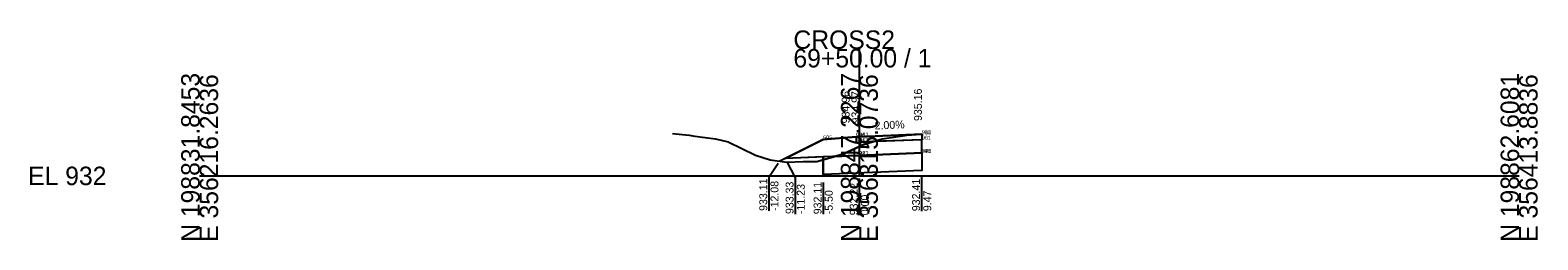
# Model space of a CAD drawing. Extents: x -26 to 203, y -10 to 14021.
# Drawn here: x -25.7 to 202.8, y 10490.3 to 10522.1 of the extents above; entities that cross this region are included whole.
import ezdxf

# ---------------------------------------------------------------- set-up
doc = ezdxf.new("R2010")
doc.units = 0
for name, color, linetype in [('Default', 7, 'Continuous'), ('P_E_XS_Ground', 7, 'Continuous'), ('P_XS', 7, 'Continuous'), ('P_XS_Bold', 7, 'Continuous'), ('P_XS_EAR_CommonGrnd', 7, 'Continuous'), ('P_XS_Lane', 7, 'Continuous'), ('P_XS_Rock', 7, 'Continuous')]:
    doc.layers.add(name, color=color, linetype=linetype)

msp = doc.modelspace()

# ---------------------------------------------------------------- linework, layer by layer
at = {"layer": 'Default'}
for p, q in [((100, 10500), (100, 10519.24)), ((0, 10500), (100, 10500)), ((100, 10500), (200, 10500))]:
    msp.add_line(p, q, dxfattribs=at)
at = {"layer": 'P_E_XS_Ground'}
for p, q in [((71.66, 10506.41), (74.2, 10506.18)), ((74.2, 10506.18), (75.08, 10506)), ((75.08, 10506), (78.17, 10505.61)), ((103.45, 10505.6), (106.59, 10506.07)), ((106.59, 10506.07), (107.21, 10506.19)), ((107.21, 10506.19), (109.29, 10506.31)), ((109.29, 10506.31), (109.49, 10506.32)), ((78.17, 10505.61), (80.11, 10505.17)), ((80.11, 10505.17), (84.27, 10503.12)), ((97.48, 10503.3), (100, 10504.46)), ((100, 10504.46), (100.69, 10504.78)), ((100.69, 10504.78), (103.45, 10505.6)), ((84.27, 10503.12), (86.48, 10502.43)), ((86.48, 10502.43), (89.02, 10502.07)), ((89.02, 10502.07), (91.5, 10502.2)), ((91.5, 10502.2), (93.55, 10502.19)), ((93.55, 10502.19), (97.48, 10503.3))]:
    msp.add_line(p, q, dxfattribs=at)
at = {"layer": 'P_XS'}
for p, q in [((99.5, 10505.92), (99.5, 10505.08)), ((109.47, 10506.32), (109.47, 10505.48)), ((99.5, 10505.08), (100, 10505.1)), ((109.47, 10505.48), (99.99, 10505.1)), ((109.47, 10503.48), (99.99, 10503.1)), ((109.47, 10503.48), (109.47, 10505.48)), ((109.47, 10503.48), (109.47, 10500.81)), ((99.5, 10503.08), (88.77, 10502.65)), ((94.5, 10502.88), (94.5, 10500.21)), ((99.5, 10503.08), (100, 10503.1)), ((109.47, 10500.81), (94.5, 10500.21))]:
    msp.add_line(p, q, dxfattribs=at)
at = {"layer": 'P_XS_EAR_CommonGrnd'}
for points in [[(99.5, 10505.92), (99.5, 10505.08), (99.99, 10505.1), (100, 10505.1), (102.07, 10505.19), (100.69, 10504.78), (100, 10504.46), (97.48, 10503.3), (96.26, 10502.95), (94.5, 10502.88), (88.77, 10502.65), (94.5, 10505.52)], [(99.5, 10505.92), (99.5, 10505.08), (99.99, 10505.1), (100, 10505.1), (102.07, 10505.19), (103.45, 10505.6), (106.59, 10506.07), (107.21, 10506.19), (109.29, 10506.31), (109.47, 10506.32), (100, 10505.94)], [(109.47, 10506.32), (109.47, 10505.48), (102.07, 10505.19), (103.45, 10505.6), (106.59, 10506.07), (107.21, 10506.19), (109.29, 10506.31)], [(99.99, 10503.1), (100, 10503.1), (109.47, 10503.48), (109.47, 10500.81), (94.5, 10500.21), (94.5, 10502.46), (96.26, 10502.95), (99.5, 10503.08)], [(99.99, 10503.1), (100, 10503.1), (109.47, 10503.48), (109.47, 10505.48), (102.07, 10505.19), (100.69, 10504.78), (100, 10504.46), (97.48, 10503.3), (96.26, 10502.95), (99.5, 10503.08)], [(89.02, 10502.07), (91.5, 10502.2), (93.55, 10502.19), (94.5, 10502.46), (94.5, 10502.88), (88.77, 10502.65), (87.92, 10502.23)], [(94.5, 10502.46), (96.26, 10502.95), (94.5, 10502.88)]]:
    msp.add_lwpolyline(points, close=True, dxfattribs=at)
at = {"layer": 'P_XS_Lane'}
for p, q in [((99.5, 10505.92), (94.5, 10505.52)), ((99.5, 10505.92), (100, 10505.94)), ((100, 10505.94), (109.47, 10506.32)), ((94.5, 10505.52), (87.92, 10502.23))]:
    msp.add_line(p, q, dxfattribs=at)
at = {"layer": 'P_XS_Rock'}
for p, q in [((87.68, 10501.86), (86.28, 10499.78)), ((90.27, 10499.81), (89.06, 10502.12)), ((86.28, 10499.78), (86.28, 10494.69)), ((90.27, 10499.81), (90.27, 10494.22)), ((94.51, 10498.98), (94.51, 10494.18)), ((99.99, 10499.62), (99.99, 10494.03)), ((109.44, 10499.94), (109.44, 10494.65))]:
    msp.add_line(p, q, dxfattribs=at)

# ---------------------------------------------------------------- texts
at = {"layer": 'Default'}
for s, p in [('CROSS2', (90, 10519.24)), ('69+50.00 / 1', (90, 10516.44)), ('EL 932', (-26, 10498.6))]:
    msp.add_text(s, height=2.8, dxfattribs=at).set_placement(p)
for s, p in [('N 198831.8453', (0, 10490)), ('E 356216.2636', (2.8, 10490)), ('N 198847.2267', (100, 10490)), ('E 356315.0736', (102.8, 10490)), ('N 198862.6081', (200, 10490)), ('E 356413.8836', (202.8, 10490))]:
    msp.add_text(s, height=2.8, rotation=90, dxfattribs=at).set_placement(p)
at = {"layer": 'P_XS_Bold'}
for s, p in [('505', (94.5, 10505.52)), ('951', (99.5, 10505.92)), ('9', (99.5, 10505.92)), ('900', (99.5, 10505.92)), ('961', (99.5, 10505.08)), ('962', (99.99, 10505.1)), ('952', (100, 10505.94)), ('952', (100, 10505.94)), ('962', (100, 10505.1)), ('951', (109.47, 10506.32)), ('9', (109.47, 10506.32)), ('900', (109.47, 10506.32)), ('910', (109.47, 10506.32)), ('961', (109.47, 10505.48)), ('971', (99.5, 10503.08)), ('998', (99.5, 10503.08)), ('972', (99.99, 10503.1)), ('972', (100, 10503.1)), ('540', (109.47, 10503.48)), ('971', (109.47, 10503.48)), ('998', (109.47, 10503.48))]:
    msp.add_text(s, height=0.6, dxfattribs=at).set_placement(p)
at = {"layer": 'P_XS_Rock'}
for s, rotation, p in [('934.96', 90, (98.52, 10507.96)), ('934.97', 90, (100, 10507.94)), ('934.97', 90, (100, 10507.94)), ('934.97', 90, (100, 10507.94)), ('934.97', 90, (100, 10507.94)), ('935.16', 90, (109.47, 10508.32)), ('2.00%', 2.2906, (102.33, 10507.03)), ('933.11', 90, (86.03, 10494.69)), ('-12.08', 90, (87.73, 10494.69)), ('933.33', 90, (90.02, 10494.22)), ('932.11', 90, (94.26, 10494.18)), ('932.22', 90, (99.74, 10494.03)), ('932.41', 90, (109.19, 10494.65)), ('-11.23', 90, (91.72, 10494.22)), ('-5.50', 90, (95.96, 10494.18)), ('0.00', 90, (101.44, 10494.03)), ('9.47', 90, (110.89, 10494.65))]:
    msp.add_text(s, height=1.2, rotation=rotation, dxfattribs=at).set_placement(p)

doc.saveas('drawing.dxf')
